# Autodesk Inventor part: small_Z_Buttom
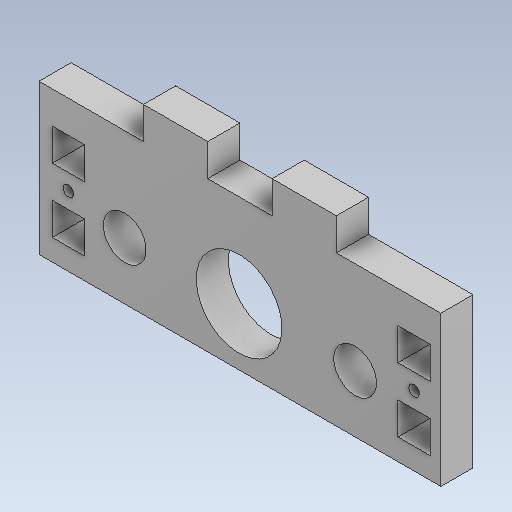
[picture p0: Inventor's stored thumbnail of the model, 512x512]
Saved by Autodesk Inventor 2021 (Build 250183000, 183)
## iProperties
Created: 2026-10
Part Number: small_Z_Buttom
Material: Steel
Document SubType Name: Modeling
Designer: hp
Density: 7.85 g/cm^3
Appearance: Default
Author: hp
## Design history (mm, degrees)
feature "Body1"
body "Solid1"
